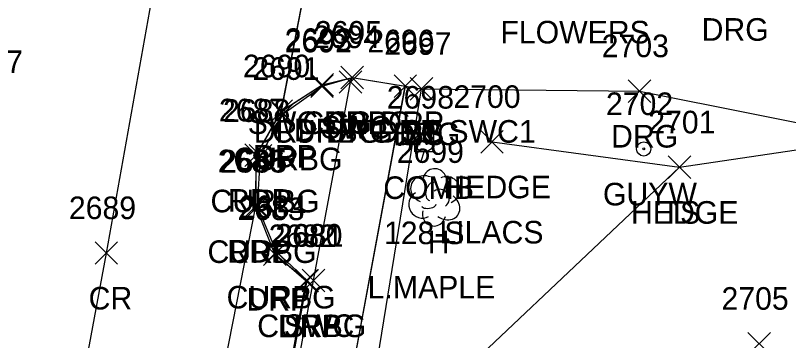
# Model space of a CAD drawing. Extents: x 1554668 to 1563881, y 831386 to 834374.
# Drawn here: x 1562220.7 to 1562289.1, y 832516.7 to 832545.4 of the extents above; entities that cross this region are included whole.
import ezdxf

# ---------------------------------------------------------------- set-up
doc = ezdxf.new("R2010")
doc.units = 0
for name, color, linetype in [('L_A', 7, 'Continuous'), ('L_C', 7, 'Continuous'), ('L_I', 7, 'Continuous'), ('L_TIC', 7, 'Continuous'), ('LAHR', 7, 'Continuous'), ('LELB', 7, 'Continuous'), ('LTD', 7, 'Continuous'), ('P_A', 7, 'Continuous'), ('P_I', 7, 'Continuous'), ('P_TIC', 7, 'Continuous'), ('PET', 7, 'Continuous'), ('PRC', 7, 'Continuous'), ('R_A', 7, 'Continuous'), ('R_I', 7, 'Continuous'), ('R_TIC', 7, 'Continuous'), ('RC', 7, 'Continuous'), ('RDG', 7, 'Continuous'), ('RDP', 7, 'Continuous'), ('RSW', 7, 'Continuous'), ('U_A', 7, 'Continuous'), ('U_C', 7, 'Continuous'), ('U_I', 7, 'Continuous'), ('UP', 7, 'Continuous'), ('UPGW', 7, 'Continuous')]:
    doc.layers.add(name, color=color, linetype=linetype)

msp = doc.modelspace()

# ---------------------------------------------------------------- linework, layer by layer
at = {"layer": 'L_TIC'}
for points in [[(1562255.645, 832537.949), (1562257.645, 832539.949)], [(1562257.645, 832537.949), (1562255.645, 832539.949)], [(1562261.88, 832533.247), (1562263.88, 832535.247)], [(1562263.88, 832533.247), (1562261.88, 832535.247)], [(1562278.484, 832530.996), (1562280.484, 832532.996)], [(1562280.484, 832530.996), (1562278.484, 832532.996)], [(1562278.484, 832530.996), (1562280.484, 832532.996)], [(1562280.484, 832530.996), (1562278.484, 832532.996)], [(1562285.535, 832515.382), (1562287.535, 832517.382)], [(1562287.535, 832515.382), (1562285.535, 832517.382)]]:
    msp.add_lwpolyline(points, dxfattribs=at)
at = {"layer": 'LAHR'}
for points in [[(1562262.88, 832534.247), (1562279.484, 832531.996)], [(1562262.885, 832534.247), (1562279.485, 832531.989)], [(1562262.885, 832534.247), (1562279.485, 832531.989)], [(1562262.885, 832534.247), (1562279.485, 832531.989)]]:
    msp.add_lwpolyline(points, dxfattribs=at)
at = {"layer": 'LELB'}
for points in [[(1562251.651, 832508.22), (1562256.645, 832538.949)], [(1562251.655, 832508.219), (1562256.647, 832538.942)], [(1562251.655, 832508.219), (1562256.647, 832538.942)], [(1562251.655, 832508.219), (1562256.647, 832538.942)], [(1562253.835, 832507.76), (1562279.484, 832531.996), (1562296.805, 832534.581)], [(1562253.84, 832507.76), (1562279.485, 832531.989), (1562296.806, 832534.575)], [(1562253.84, 832507.76), (1562279.485, 832531.989), (1562296.806, 832534.575)], [(1562253.84, 832507.76), (1562279.485, 832531.989), (1562296.806, 832534.575)]]:
    msp.add_lwpolyline(points, dxfattribs=at)
at = {"layer": 'LTD'}
msp.add_line((1562257.758, 832529.383), (1562257.758, 832529.383), dxfattribs=at)
msp.add_line((1562257.758, 832529.383), (1562257.758, 832529.383), dxfattribs=at)
msp.add_arc((1562257.804, 832530.817), 1.047, 335.52715, 180.95627, dxfattribs=at)
for centre, major_axis, ratio, start_param, end_param in [((1562256.966, 832530.05), (1.21, -0.512), 0.895232, 1.570796, 4.712389), ((1562258.799, 832529.967), (-1.141, -0.483), 0.949671, 1.570796, 4.712389), ((1562257.549, 832529.842), (-0.208, -0.792), 0.645439, 3.141593, 6.283185), ((1562256.674, 832528.675), (0.584, -1.042), 0.959034, 3.141593, 6.283185), ((1562258.258, 832529.217), (-0.5, 0.667), 0.989748, 3.141593, 6.283185), ((1562258.758, 832528.55), (-1.09, 0.792), 0.841452, 1.570796, 4.712389), ((1562257.299, 832528.633), (-0.625, -0.083), 0.423636, 0, 3.141593), ((1562257.758, 832527.883), (0.265, 1.061), 0.942809, 1.570796, 4.712389)]:
    msp.add_ellipse(centre, major_axis=major_axis, ratio=ratio, start_param=start_param, end_param=end_param, dxfattribs=at)
at = {"layer": 'P_TIC'}
for points in [[(1562243.222, 832535.962), (1562245.222, 832537.962)], [(1562245.222, 832535.962), (1562243.222, 832537.962)], [(1562241.008, 832532.059), (1562243.008, 832534.059)], [(1562243.008, 832532.059), (1562241.008, 832534.059)], [(1562240.957, 832527.547), (1562242.957, 832529.547)], [(1562242.957, 832527.547), (1562240.957, 832529.547)], [(1562227.731, 832523.404), (1562229.731, 832525.404)], [(1562229.731, 832523.404), (1562227.731, 832525.404)]]:
    msp.add_lwpolyline(points, dxfattribs=at)
at = {"layer": 'PET'}
for points in [[(1562193.167, 832267.13), (1562201.146, 832309.703), (1562207.218, 832342.575), (1562208.538, 832349.445), (1562211.679, 832366.094), (1562212.836, 832373.113), (1562216.871, 832394.677), (1562221.784, 832421.25), (1562225.693, 832442.111), (1562233.351, 832484.078), (1562234.186, 832488.931), (1562241.957, 832528.547), (1562242.008, 832533.059), (1562244.222, 832536.962), (1562248.062, 832556.9), (1562257.295, 832610.994), (1562261.428, 832631.195), (1562266.166, 832657.988), (1562270.512, 832679.644), (1562276.163, 832714.072), (1562282.459, 832748.505), (1562288.68, 832787.056), (1562293.2, 832810.286), (1562300.396, 832850.568)], [(1562193.171, 832267.13), (1562201.149, 832309.703), (1562207.222, 832342.574), (1562208.542, 832349.444), (1562211.683, 832366.093), (1562212.84, 832373.112), (1562216.874, 832394.674), (1562221.788, 832421.249), (1562225.694, 832442.106), (1562233.354, 832484.072), (1562234.19, 832488.925), (1562241.961, 832528.547), (1562242.013, 832533.06), (1562244.225, 832536.956), (1562248.066, 832556.896), (1562257.301, 832610.991), (1562261.43, 832631.195), (1562266.171, 832657.989), (1562270.514, 832679.643), (1562276.166, 832714.07), (1562282.463, 832748.508), (1562288.682, 832787.054), (1562293.205, 832810.287), (1562300.398, 832850.573)], [(1562193.171, 832267.13), (1562201.149, 832309.703), (1562207.222, 832342.574), (1562208.542, 832349.444), (1562211.683, 832366.093), (1562212.84, 832373.112), (1562216.874, 832394.674), (1562221.788, 832421.249), (1562225.694, 832442.106), (1562233.354, 832484.072), (1562234.19, 832488.925), (1562241.961, 832528.547), (1562242.013, 832533.06), (1562244.225, 832536.956), (1562248.066, 832556.896), (1562257.301, 832610.991), (1562261.43, 832631.195), (1562266.171, 832657.989), (1562270.514, 832679.643), (1562276.166, 832714.07), (1562282.463, 832748.508), (1562288.682, 832787.054), (1562293.205, 832810.287), (1562300.398, 832850.573)], [(1562193.171, 832267.13), (1562201.149, 832309.703), (1562207.222, 832342.574), (1562208.542, 832349.444), (1562211.683, 832366.093), (1562212.84, 832373.112), (1562216.874, 832394.674), (1562221.788, 832421.249), (1562225.694, 832442.106), (1562233.354, 832484.072), (1562234.19, 832488.925), (1562241.961, 832528.547), (1562242.013, 832533.06), (1562244.225, 832536.956), (1562248.066, 832556.896), (1562257.301, 832610.991), (1562261.43, 832631.195), (1562266.171, 832657.989), (1562270.514, 832679.643), (1562276.166, 832714.07), (1562282.463, 832748.508), (1562288.682, 832787.054), (1562293.205, 832810.287), (1562300.398, 832850.573)]]:
    msp.add_lwpolyline(points, dxfattribs=at)
at = {"layer": 'PRC'}
for points in [[(1562110.411, 831900.561), (1562120.308, 831948.457), (1562125.632, 831978.446), (1562135.485, 832029.35), (1562141.594, 832061.08), (1562148.973, 832098.697), (1562154.265, 832127.132), (1562163.42, 832175.531), (1562172.445, 832223.752), (1562181.394, 832270.005), (1562188.915, 832310.797), (1562198.31, 832360.399), (1562204.785, 832396.81), (1562210.164, 832423.469), (1562217.979, 832466.497), (1562228.735, 832524.397), (1562236.126, 832565.741), (1562244.769, 832613.731), (1562253.108, 832660.756), (1562257.149, 832682.207), (1562263.128, 832717.528), (1562269.494, 832752.574), (1562275.778, 832790.076), (1562288.132, 832857.633)], [(1562110.411, 831900.561), (1562120.308, 831948.457), (1562125.632, 831978.446), (1562135.485, 832029.35), (1562141.594, 832061.08), (1562148.973, 832098.697), (1562154.265, 832127.132), (1562163.42, 832175.531), (1562172.445, 832223.752), (1562181.394, 832270.005), (1562188.915, 832310.797), (1562198.31, 832360.399), (1562204.785, 832396.81), (1562210.164, 832423.469), (1562217.979, 832466.497), (1562228.735, 832524.397), (1562236.126, 832565.741), (1562244.769, 832613.731), (1562253.108, 832660.756), (1562257.149, 832682.207), (1562263.128, 832717.528), (1562269.494, 832752.574), (1562275.778, 832790.076), (1562288.132, 832857.633)], [(1562110.411, 831900.561), (1562120.308, 831948.457), (1562125.632, 831978.446), (1562135.485, 832029.35), (1562141.594, 832061.08), (1562148.973, 832098.697), (1562154.265, 832127.132), (1562163.42, 832175.531), (1562172.445, 832223.752), (1562181.394, 832270.005), (1562188.915, 832310.797), (1562198.31, 832360.399), (1562204.785, 832396.81), (1562210.164, 832423.469), (1562217.979, 832466.497), (1562228.735, 832524.397), (1562236.126, 832565.741), (1562244.769, 832613.731), (1562253.108, 832660.756), (1562257.149, 832682.207), (1562263.128, 832717.528), (1562269.494, 832752.574), (1562275.778, 832790.076), (1562288.132, 832857.633)], [(1562110.416, 831900.563), (1562120.309, 831948.456), (1562125.634, 831978.446), (1562135.488, 832029.349), (1562141.594, 832061.08), (1562148.971, 832098.698), (1562154.265, 832127.137), (1562163.419, 832175.534), (1562172.445, 832223.751), (1562181.389, 832270.011), (1562188.91, 832310.801), (1562198.306, 832360.397), (1562204.781, 832396.813), (1562210.163, 832423.475), (1562217.975, 832466.5), (1562228.731, 832524.404), (1562236.122, 832565.744), (1562244.766, 832613.73), (1562253.104, 832660.756), (1562257.145, 832682.206), (1562263.124, 832717.525), (1562269.49, 832752.57), (1562275.776, 832790.077), (1562288.125, 832857.632)]]:
    msp.add_lwpolyline(points, dxfattribs=at)
at = {"layer": 'R_TIC'}
for points in [[(1562249.495, 832538.937), (1562251.495, 832540.937)], [(1562251.495, 832538.937), (1562249.495, 832540.937)], [(1562249.495, 832538.937), (1562251.495, 832540.937)], [(1562251.495, 832538.937), (1562249.495, 832540.937)], [(1562249.495, 832538.937), (1562251.495, 832540.937)], [(1562251.495, 832538.937), (1562249.495, 832540.937)], [(1562246.826, 832538.168), (1562248.826, 832540.168)], [(1562248.826, 832538.168), (1562246.826, 832540.168)], [(1562246.844, 832538.293), (1562248.844, 832540.293)], [(1562248.844, 832538.293), (1562246.844, 832540.293)], [(1562249.338, 832538.541), (1562251.338, 832540.541)], [(1562251.338, 832538.541), (1562249.338, 832540.541)], [(1562254.201, 832538.171), (1562256.201, 832540.171)], [(1562256.201, 832538.171), (1562254.201, 832540.171)], [(1562254.201, 832538.171), (1562256.201, 832540.171)], [(1562256.201, 832538.171), (1562254.201, 832540.171)], [(1562254.201, 832538.171), (1562256.201, 832540.171)], [(1562256.201, 832538.171), (1562254.201, 832540.171)], [(1562255.645, 832537.949), (1562257.645, 832539.949)], [(1562257.645, 832537.949), (1562255.645, 832539.949)], [(1562274.93, 832537.739), (1562276.93, 832539.739)], [(1562276.93, 832537.739), (1562274.93, 832539.739)], [(1562243.222, 832535.962), (1562245.222, 832537.962)], [(1562245.222, 832535.962), (1562243.222, 832537.962)], [(1562243.397, 832535.73), (1562245.397, 832537.73)], [(1562245.397, 832535.73), (1562243.397, 832537.73)], [(1562241.372, 832532.008), (1562243.372, 832534.008)], [(1562243.372, 832532.008), (1562241.372, 832534.008)], [(1562240.957, 832527.547), (1562242.957, 832529.547)], [(1562242.957, 832527.547), (1562240.957, 832529.547)], [(1562241.104, 832527.524), (1562243.104, 832529.524)], [(1562243.104, 832527.524), (1562241.104, 832529.524)], [(1562242.795, 832523.496), (1562244.795, 832525.496)], [(1562244.795, 832523.496), (1562242.795, 832525.496)], [(1562242.643, 832523.313), (1562244.643, 832525.313)], [(1562244.643, 832523.313), (1562242.643, 832525.313)], [(1562245.418, 832520.93), (1562247.418, 832522.93)], [(1562247.418, 832520.93), (1562245.418, 832522.93)], [(1562245.507, 832520.959), (1562247.507, 832522.959)], [(1562247.507, 832520.959), (1562245.507, 832522.959)], [(1562246.081, 832520.971), (1562248.081, 832522.971)], [(1562248.081, 832520.971), (1562246.081, 832522.971)]]:
    msp.add_lwpolyline(points, dxfattribs=at)
at = {"layer": 'RC'}
for points in [[(1562235.121, 832488.716), (1562234.186, 832488.931), (1562236.41, 832493.281), (1562238.118, 832494.91), (1562241.939, 832496.676), (1562246.507, 832521.959), (1562243.795, 832524.496), (1562242.104, 832528.524), (1562242.372, 832533.008), (1562244.397, 832536.73), (1562247.826, 832539.168), (1562250.495, 832539.937)], [(1562235.125, 832488.716), (1562234.19, 832488.925), (1562236.413, 832493.273), (1562238.121, 832494.908), (1562241.943, 832496.677), (1562246.512, 832521.96), (1562243.799, 832524.495), (1562242.108, 832528.524), (1562242.376, 832533.003), (1562244.401, 832536.731), (1562247.83, 832539.164), (1562250.499, 832539.938)], [(1562235.125, 832488.716), (1562234.19, 832488.925), (1562236.413, 832493.273), (1562238.121, 832494.908), (1562241.943, 832496.677), (1562246.512, 832521.96), (1562243.799, 832524.495), (1562242.108, 832528.524), (1562242.376, 832533.003), (1562244.401, 832536.731), (1562247.83, 832539.164), (1562250.499, 832539.938)], [(1562235.125, 832488.716), (1562234.19, 832488.925), (1562236.413, 832493.273), (1562238.121, 832494.908), (1562241.943, 832496.677), (1562246.512, 832521.96), (1562243.799, 832524.495), (1562242.108, 832528.524), (1562242.376, 832533.003), (1562244.401, 832536.731), (1562247.83, 832539.164), (1562250.499, 832539.938)]]:
    msp.add_lwpolyline(points, dxfattribs=at)
at = {"layer": 'RDG'}
for points in [[(1562255.201, 832539.171), (1562256.645, 832538.949), (1562275.93, 832538.739), (1562296.805, 832534.581)], [(1562255.204, 832539.166), (1562256.647, 832538.942), (1562275.932, 832538.733), (1562296.806, 832534.575)], [(1562255.204, 832539.166), (1562256.647, 832538.942), (1562275.932, 832538.733), (1562296.806, 832534.575)], [(1562255.204, 832539.166), (1562256.647, 832538.942), (1562275.932, 832538.733), (1562296.806, 832534.575)]]:
    msp.add_lwpolyline(points, dxfattribs=at)
at = {"layer": 'RDP'}
for points in [[(1562244.222, 832536.962), (1562247.844, 832539.293), (1562250.495, 832539.937), (1562255.201, 832539.171)], [(1562244.225, 832536.956), (1562247.848, 832539.291), (1562250.499, 832539.938), (1562255.204, 832539.166)], [(1562244.225, 832536.956), (1562247.848, 832539.291), (1562250.499, 832539.938), (1562255.204, 832539.166)], [(1562244.225, 832536.956), (1562247.848, 832539.291), (1562250.499, 832539.938), (1562255.204, 832539.166)], [(1562234.186, 832488.931), (1562236.297, 832493.356), (1562237.987, 832495.002), (1562241.854, 832496.984), (1562246.418, 832521.93), (1562243.643, 832524.313), (1562241.957, 832528.547)], [(1562234.19, 832488.925), (1562236.301, 832493.357), (1562237.992, 832495.003), (1562241.857, 832496.981), (1562246.421, 832521.926), (1562243.647, 832524.312), (1562241.961, 832528.547)], [(1562234.19, 832488.925), (1562236.301, 832493.357), (1562237.992, 832495.003), (1562241.857, 832496.981), (1562246.421, 832521.926), (1562243.647, 832524.312), (1562241.961, 832528.547)], [(1562234.19, 832488.925), (1562236.301, 832493.357), (1562237.992, 832495.003), (1562241.857, 832496.981), (1562246.421, 832521.926), (1562243.647, 832524.312), (1562241.961, 832528.547)]]:
    msp.add_lwpolyline(points, dxfattribs=at)
at = {"layer": 'RSW'}
for points in [[(1562199.278, 832264.932), (1562207.605, 832308.712), (1562213.507, 832341.19), (1562215.246, 832350.285), (1562217.945, 832364.493), (1562219.157, 832371.002), (1562223.319, 832393.848), (1562228.316, 832419.906), (1562233.829, 832449.886), (1562234.728, 832454.744), (1562235.989, 832461.711), (1562236.957, 832466.575), (1562238.293, 832473.34), (1562239.785, 832483.044), (1562240.805, 832487.84), (1562242.418, 832496.743), (1562247.081, 832521.971), (1562250.338, 832539.541), (1562250.495, 832539.937)], [(1562199.281, 832264.931), (1562207.608, 832308.712), (1562213.511, 832341.189), (1562215.249, 832350.286), (1562217.949, 832364.492), (1562219.161, 832370.998), (1562223.323, 832393.851), (1562228.319, 832419.899), (1562233.833, 832449.883), (1562234.732, 832454.742), (1562235.992, 832461.703), (1562236.961, 832466.574), (1562238.296, 832473.337), (1562239.788, 832483.042), (1562240.808, 832487.833), (1562242.422, 832496.742), (1562247.085, 832521.97), (1562250.341, 832539.537), (1562250.499, 832539.938)], [(1562199.281, 832264.931), (1562207.608, 832308.712), (1562213.511, 832341.189), (1562215.249, 832350.286), (1562217.949, 832364.492), (1562219.161, 832370.998), (1562223.323, 832393.851), (1562228.319, 832419.899), (1562233.833, 832449.883), (1562234.732, 832454.742), (1562235.992, 832461.703), (1562236.961, 832466.574), (1562238.296, 832473.337), (1562239.788, 832483.042), (1562240.808, 832487.833), (1562242.422, 832496.742), (1562247.085, 832521.97), (1562250.341, 832539.537), (1562250.499, 832539.938)], [(1562199.281, 832264.931), (1562207.608, 832308.712), (1562213.511, 832341.189), (1562215.249, 832350.286), (1562217.949, 832364.492), (1562219.161, 832370.998), (1562223.323, 832393.851), (1562228.319, 832419.899), (1562233.833, 832449.883), (1562234.732, 832454.742), (1562235.992, 832461.703), (1562236.961, 832466.574), (1562238.296, 832473.337), (1562239.788, 832483.042), (1562240.808, 832487.833), (1562242.422, 832496.742), (1562247.085, 832521.97), (1562250.341, 832539.537), (1562250.499, 832539.938)], [(1562228.277, 832393.371), (1562233.083, 832419.36), (1562238.49, 832449.192), (1562239.584, 832454.599), (1562240.799, 832460.633), (1562241.627, 832465.536), (1562242.677, 832470.434), (1562243.41, 832475.219), (1562244.243, 832480.091), (1562245.508, 832480.058), (1562245.776, 832483.282), (1562245, 832483.496), (1562246.121, 832490.273), (1562248.716, 832504.749), (1562250.872, 832504.451), (1562251.651, 832508.22), (1562249.553, 832508.685), (1562255.201, 832539.171)], [(1562228.28, 832393.367), (1562233.087, 832419.355), (1562238.49, 832449.188), (1562239.589, 832454.598), (1562240.8, 832460.627), (1562241.629, 832465.529), (1562242.68, 832470.432), (1562243.414, 832475.218), (1562244.247, 832480.09), (1562245.509, 832480.051), (1562245.778, 832483.275), (1562245.002, 832483.492), (1562246.125, 832490.271), (1562248.721, 832504.75), (1562250.877, 832504.452), (1562251.655, 832508.219), (1562249.556, 832508.681), (1562255.204, 832539.166)], [(1562228.28, 832393.367), (1562233.087, 832419.355), (1562238.49, 832449.188), (1562239.589, 832454.598), (1562240.8, 832460.627), (1562241.629, 832465.529), (1562242.68, 832470.432), (1562243.414, 832475.218), (1562244.247, 832480.09), (1562245.509, 832480.051), (1562245.778, 832483.275), (1562245.002, 832483.492), (1562246.125, 832490.271), (1562248.721, 832504.75), (1562250.877, 832504.452), (1562251.655, 832508.219), (1562249.556, 832508.681), (1562255.204, 832539.166)], [(1562228.28, 832393.367), (1562233.087, 832419.355), (1562238.49, 832449.188), (1562239.589, 832454.598), (1562240.8, 832460.627), (1562241.629, 832465.529), (1562242.68, 832470.432), (1562243.414, 832475.218), (1562244.247, 832480.09), (1562245.509, 832480.051), (1562245.778, 832483.275), (1562245.002, 832483.492), (1562246.125, 832490.271), (1562248.721, 832504.75), (1562250.877, 832504.452), (1562251.655, 832508.219), (1562249.556, 832508.681), (1562255.204, 832539.166)]]:
    msp.add_lwpolyline(points, dxfattribs=at)
at = {"layer": 'UP'}
for p, q in [((1562257.119, 832535.854), (1562256.869, 832535.021)), ((1562256.036, 832533.354), (1562256.036, 832535.021)), ((1562256.036, 832535.021), (1562257.702, 832535.021)), ((1562257.702, 832535.021), (1562257.702, 832533.354)), ((1562256.869, 832534.188), (1562256.869, 832534.188)), ((1562257.702, 832533.354), (1562256.036, 832533.354)), ((1562256.619, 832532.521), (1562256.869, 832533.354))]:
    msp.add_line(p, q, dxfattribs=at)
msp.add_circle((1562256.869, 832534.188), 0.833, dxfattribs=at)
at = {"layer": 'UPGW'}
for radius in [0.625, 0.0833]:
    msp.add_circle((1562276.306, 832533.617), radius, dxfattribs=at)

# ---------------------------------------------------------------- texts
at = {"layer": 'L_A'}
for s, p in [('BS', (1562255.086, 832533.949)), ('HEDGE', (1562258.581, 832529.247)), ('HEDGE', (1562275.185, 832526.996)), ('TS', (1562277.893, 832526.996)), ('H', (1562257.191, 832524.383))]:
    msp.add_text(s, height=2, dxfattribs=at).set_placement(p)
at = {"layer": 'L_C'}
for s, p in [('FLOWERS', (1562263.621, 832542.956)), ('LILACS', (1562258.219, 832525.247)), ('L.MAPLE', (1562251.868, 832520.383))]:
    msp.add_text(s, height=2, dxfattribs=at).set_placement(p)
at = {"layer": 'L_I'}
for s, p in [('2697', (1562253.338, 832541.949)), ('2700', (1562259.455, 832537.247)), ('2701', (1562276.712, 832534.996)), ('2701', (1562276.712, 832534.996)), ('2699', (1562254.443, 832532.383)), ('2705', (1562283.196, 832519.382))]:
    msp.add_text(s, height=2, dxfattribs=at).set_placement(p)
at = {"layer": 'P_A'}
for s, p in [('RDP', (1562241.71, 832531.962)), ('RDP', (1562239.497, 832528.059)), ('RDP', (1562239.445, 832523.547)), ('CR', (1562227.164, 832519.404))]:
    msp.add_text(s, height=2, dxfattribs=at).set_placement(p)
at = {"layer": 'P_I'}
for s, p in [('1917', (1562215.403, 832540.337)), ('2690', (1562240.828, 832539.962)), ('2687', (1562238.701, 832536.059)), ('2686', (1562238.595, 832531.547)), ('2689', (1562225.416, 832527.404))]:
    msp.add_text(s, height=2, dxfattribs=at).set_placement(p)
at = {"layer": 'R_A'}
for s, p in [('DRG', (1562281.436, 832543.194)), ('SWC CG DRP', (1562241.243, 832534.937)), ('CURBG', (1562246.078, 832534.937)), ('SWC', (1562247.7, 832534.541)), ('DRP', (1562247.983, 832534.937)), ('DRP DRG ST SWC1', (1562241.784, 832534.171)), ('CURBG', (1562243.409, 832534.168)), ('DRP', (1562245.332, 832534.293)), ('DRG', (1562252.689, 832534.171)), ('DRP', (1562252.689, 832534.171)), ('DRG', (1562254.133, 832533.949)), ('DRG', (1562273.418, 832533.739)), ('CURBG', (1562239.98, 832531.73)), ('DRP', (1562241.71, 832531.962)), ('CURBG', (1562237.955, 832528.008)), ('CURBG', (1562237.686, 832523.524)), ('DRP', (1562239.445, 832523.547)), ('CURBG', (1562239.378, 832519.496)), ('DRP', (1562241.131, 832519.313)), ('CURBG', (1562242.09, 832516.959)), ('DRP', (1562243.906, 832516.93)), ('SWC', (1562244.444, 832516.971))]:
    msp.add_text(s, height=2, dxfattribs=at).set_placement(p)
at = {"layer": 'R_I'}
for s, p in [('2695', (1562247.188, 832542.937)), ('2695', (1562247.188, 832542.937)), ('2695', (1562247.188, 832542.937)), ('2692', (1562244.519, 832542.168)), ('2693', (1562244.537, 832542.293)), ('2694', (1562247.03, 832542.541)), ('2696', (1562251.839, 832542.171)), ('2696', (1562251.839, 832542.171)), ('2696', (1562251.839, 832542.171)), ('2697', (1562253.338, 832541.949)), ('2703', (1562272.591, 832541.739)), ('2690', (1562240.828, 832539.962)), ('2691', (1562241.657, 832539.73)), ('2688', (1562239.065, 832536.008)), ('2686', (1562238.595, 832531.547)), ('2685', (1562238.797, 832531.524)), ('2683', (1562240.336, 832527.313)), ('2684', (1562240.488, 832527.496)), ('2682', (1562243.111, 832524.93)), ('2680', (1562243.688, 832524.971)), ('2681', (1562243.767, 832524.959))]:
    msp.add_text(s, height=2, dxfattribs=at).set_placement(p)
at = {"layer": 'U_A'}
for s, p in [('COMB', (1562253.255, 832529.188)), ('GUYW', (1562272.7, 832528.617))]:
    msp.add_text(s, height=2, dxfattribs=at).set_placement(p)
at = {"layer": 'U_C'}
msp.add_text('128-S', height=2, dxfattribs=at).set_placement((1562253.31, 832525.188))
at = {"layer": 'U_I'}
for s, p in [('2698', (1562253.562, 832537.188)), ('2702', (1562272.967, 832536.617))]:
    msp.add_text(s, height=2, dxfattribs=at).set_placement(p)

doc.saveas('drawing.dxf')
